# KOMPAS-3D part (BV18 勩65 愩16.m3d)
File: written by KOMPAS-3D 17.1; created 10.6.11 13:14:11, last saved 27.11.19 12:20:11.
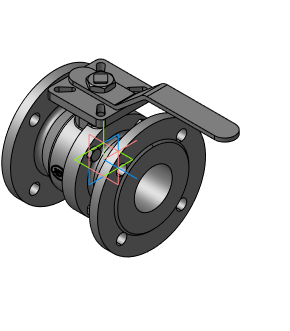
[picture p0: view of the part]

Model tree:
1. Плоскость XY
2. Плоскость ZX
3. Плоскость ZY
4. Ось X
5. Ось Y
6. Ось Z
7. Начало координат
8. Операция без истории:2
